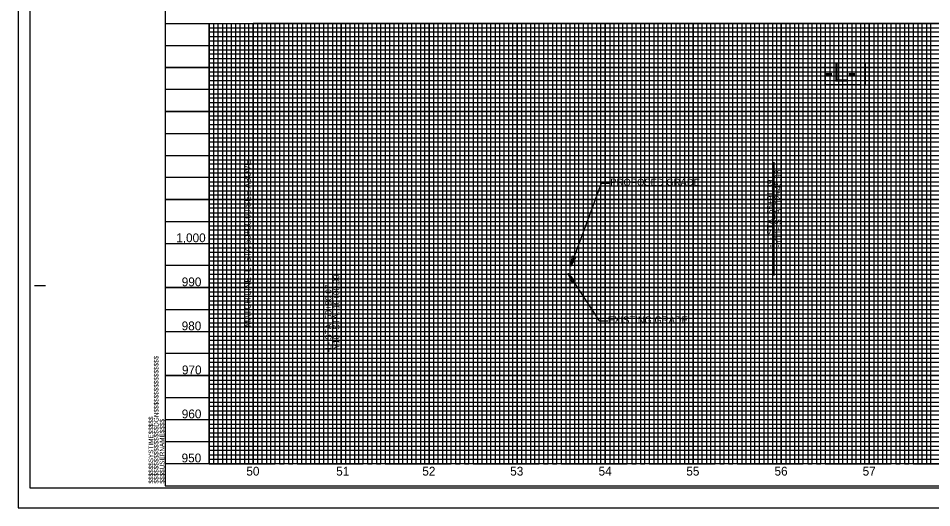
# Model space of a CAD drawing. Extents: x 1626113 to 1628102, y 900759 to 901859.
# Drawn here: x 1626113 to 1627151, y 900759 to 901315 of the extents above; entities that cross this region are included whole.
import ezdxf

# ---------------------------------------------------------------- set-up
doc = ezdxf.new("R2010")
doc.units = 0
for name, color, linetype in [('Default', 7, 'Continuous'), ('Matchline', 7, 'Continuous'), ('Matchline Text', 7, 'Continuous'), ('Prop DSN Text', 7, 'Continuous'), ('Prop PHM Black Shape', 7, 'Continuous'), ('Prop Plan Preparation Cover Label', 7, 'Continuous'), ('Scratch_Level_2', 7, 'Continuous'), ('Sheet Cutting Line CELL', 7, 'Continuous'), ('Sheet DOT Grid CELL', 7, 'Continuous'), ('Sheet Layout Profile Border Port 2', 7, 'Continuous'), ('Sheet Plot Border Inside CELL', 7, 'Continuous'), ('Sheet Plot Border Outside CELL', 7, 'Continuous'), ('Sheet Profile CELL', 7, 'Continuous'), ('Sheet Profile Grid Major CELL', 7, 'Continuous'), ('Sheet Profile Grid Middle CELL', 7, 'Continuous'), ('Typical Terminator CELL', 7, 'Continuous')]:
    doc.layers.add(name, color=color, linetype=linetype)

msp = doc.modelspace()

# ---------------------------------------------------------------- linework, layer by layer
at = {"layer": 'Matchline'}
msp.add_line((1626379.9, 900809.4), (1626379.9, 901309.4), dxfattribs=at)
at = {"layer": 'Prop DSN Text'}
for p, q in [((1626740.7, 901033.6), (1626775.7, 901127.8)), ((1626775.7, 901127.8), (1626785.7, 901127.8)), ((1626737.9, 901025.2), (1626772.9, 900971.5)), ((1626772.9, 900971.5), (1626782.9, 900971.5))]:
    msp.add_line(p, q, dxfattribs=at)
msp.add_lwpolyline([(1627029.9, 901264.4), (1627069.9, 901264.4), (1627069.9, 901239.4), (1627029.9, 901239.4)], close=True, dxfattribs=at)
for points in [[(1626971.7, 901022.9), (1626971.7, 901151.6)], [(1626469.9, 901046.4), (1626470, 900935.5)]]:
    msp.add_lwpolyline(points, dxfattribs=at)
at = {"layer": 'Prop PHM Black Shape'}
msp.add_lwpolyline([(1627024.9, 901264.4), (1627075, 901264.4), (1627075, 901239.2), (1627024.9, 901239.2)], close=True, dxfattribs=at)
at = {"layer": 'Prop Plan Preparation Cover Label'}
for p, q in [((1626329.9, 901304.2), (1627729.9, 901304.2)), ((1627729.9, 901299.2), (1626329.9, 901299.2)), ((1626329.9, 901294.2), (1627729.9, 901294.2)), ((1627729.9, 901289.2), (1626329.9, 901289.2)), ((1626329.9, 901279.2), (1627729.9, 901279.2)), ((1627729.9, 901274.2), (1626329.9, 901274.2)), ((1626329.9, 901269.2), (1627729.9, 901269.2)), ((1627729.9, 901264.2), (1626329.9, 901264.2)), ((1626329.9, 901254.2), (1627729.9, 901254.2)), ((1627729.9, 901249.2), (1626329.9, 901249.2)), ((1626329.9, 901244.2), (1627729.9, 901244.2)), ((1627729.9, 901239.2), (1626329.9, 901239.2)), ((1626329.9, 901229.2), (1627729.9, 901229.2)), ((1627729.9, 901224.2), (1626329.9, 901224.2)), ((1626329.9, 901219.2), (1627729.9, 901219.2)), ((1627729.9, 901214.2), (1626329.9, 901214.2)), ((1626329.9, 901204.2), (1627729.9, 901204.2)), ((1627729.9, 901199.2), (1626329.9, 901199.2)), ((1626329.9, 901194.2), (1627729.9, 901194.2)), ((1627729.9, 901189.2), (1626329.9, 901189.2)), ((1626329.9, 901179.2), (1627729.9, 901179.2)), ((1627729.9, 901174.2), (1626329.9, 901174.2)), ((1626329.9, 901169.2), (1627729.9, 901169.2)), ((1627729.9, 901164.2), (1626329.9, 901164.2)), ((1626329.9, 901154.2), (1627729.9, 901154.2)), ((1627729.9, 901149.2), (1626329.9, 901149.2)), ((1626329.9, 901144.2), (1627729.9, 901144.2)), ((1627729.9, 901139.2), (1626329.9, 901139.2)), ((1626329.9, 901129.2), (1627729.9, 901129.2)), ((1627729.9, 901124.2), (1626329.9, 901124.2)), ((1626329.9, 901119.2), (1627729.9, 901119.2)), ((1627729.9, 901114.2), (1626329.9, 901114.3)), ((1626329.9, 901104.2), (1627729.9, 901104.2)), ((1627729.9, 901099.2), (1626329.9, 901099.2)), ((1626329.9, 901094.2), (1627729.9, 901094.2)), ((1627729.9, 901089.2), (1626329.9, 901089.2)), ((1626329.9, 901079.2), (1627729.9, 901079.2)), ((1627729.9, 901074.2), (1626329.9, 901074.2)), ((1626329.9, 901069.2), (1627729.9, 901069.2)), ((1627729.9, 901064.2), (1626329.9, 901064.2)), ((1626329.9, 901054.2), (1627729.9, 901054.2)), ((1627729.9, 901049.2), (1626329.9, 901049.2)), ((1626329.9, 901044.2), (1627729.9, 901044.2)), ((1627729.9, 901039.2), (1626329.9, 901039.2)), ((1626329.9, 901029.2), (1627729.9, 901029.2)), ((1627729.9, 901024.2), (1626329.9, 901024.2)), ((1626329.9, 901019.2), (1627729.9, 901019.2)), ((1627729.9, 901014.2), (1626329.9, 901014.2)), ((1626329.9, 901004.2), (1627729.9, 901004.2)), ((1627729.9, 900999.2), (1626329.9, 900999.2)), ((1626329.9, 900994.2), (1627729.9, 900994.2)), ((1627729.9, 900989.2), (1626329.9, 900989.2)), ((1626329.9, 900979.2), (1627729.9, 900979.2)), ((1627729.9, 900974.2), (1626329.9, 900974.2)), ((1626329.9, 900969.2), (1627729.9, 900969.2)), ((1627729.9, 900964.2), (1626329.9, 900964.2)), ((1626329.9, 900954.2), (1627729.9, 900954.2)), ((1627729.9, 900949.2), (1626329.9, 900949.2)), ((1626329.9, 900944.2), (1627729.9, 900944.2)), ((1627729.9, 900939.2), (1626329.9, 900939.2)), ((1626329.9, 900929.2), (1627729.9, 900929.2)), ((1627729.9, 900924.2), (1626329.9, 900924.2)), ((1626329.9, 900919.2), (1627729.9, 900919.2)), ((1627729.9, 900914.2), (1626329.9, 900914.2)), ((1626329.9, 900904.2), (1627729.9, 900904.2)), ((1627729.9, 900899.2), (1626329.9, 900899.2)), ((1626329.9, 900894.2), (1627729.9, 900894.2)), ((1627729.9, 900889.2), (1626329.9, 900889.2)), ((1626329.9, 900879.2), (1627729.9, 900879.2)), ((1627729.9, 900874.2), (1626329.9, 900874.2)), ((1626329.9, 900869.2), (1627729.9, 900869.2)), ((1627729.9, 900864.2), (1626329.9, 900864.2)), ((1626329.9, 900854.2), (1627729.9, 900854.2)), ((1627729.9, 900849.2), (1626329.9, 900849.2)), ((1626329.9, 900844.2), (1627729.9, 900844.2)), ((1627729.9, 900839.2), (1626329.9, 900839.2)), ((1626329.9, 900829.2), (1627729.9, 900829.2)), ((1627729.9, 900824.2), (1626329.9, 900824.2)), ((1626329.9, 900819.2), (1627729.9, 900819.2)), ((1626329.9, 900814.2), (1627729.9, 900814.2))]:
    msp.add_line(p, q, dxfattribs=at)
for points in [[(1626329.9, 901309.2), (1626334.9, 901309.2), (1626334.9, 900809.2), (1626339.9, 900809.2), (1626339.9, 901309.2), (1626344.9, 901309.2), (1626344.9, 900809.2), (1626349.9, 900809.2), (1626349.9, 901309.2), (1626359.9, 901309.2), (1626359.9, 900809.2), (1626364.9, 900809.2), (1626364.9, 901309.2), (1626369.9, 901309.2), (1626369.9, 900809.2), (1626374.9, 900809.2), (1626384.9, 900809.2), (1626389.9, 900809.2), (1626389.9, 901309.2), (1626394.9, 901309.2), (1626394.9, 900809.2), (1626399.9, 900809.2), (1626399.9, 901309.2), (1626409.9, 901309.2), (1626409.9, 900809.2), (1626414.9, 900809.2), (1626414.9, 901309.2), (1626419.9, 901309.2), (1626419.9, 900809.2), (1626424.9, 900809.2), (1626424.9, 901309.2), (1626434.9, 901309.2), (1626434.9, 900809.2), (1626439.9, 900809.2), (1626439.9, 901309.2), (1626444.9, 901309.2), (1626444.9, 900809.2), (1626449.9, 900809.2), (1626449.9, 901309.2), (1626459.9, 901309.2), (1626459.9, 900809.2), (1626464.9, 900809.2), (1626464.9, 901309.2), (1626469.9, 901309.2), (1626469.9, 900809.2), (1626474.9, 900809.2), (1626474.9, 901309.2), (1626484.9, 901309.2), (1626484.9, 900809.2), (1626489.9, 900809.2), (1626489.9, 901309.2), (1626494.9, 901309.2), (1626494.9, 900809.2), (1626499.9, 900809.2), (1626499.9, 901309.2), (1626509.9, 901309.2), (1626509.9, 900809.2), (1626514.9, 900809.2), (1626514.9, 901309.2), (1626519.9, 901309.2), (1626519.9, 900809.2), (1626524.9, 900809.2), (1626524.9, 901309.2), (1626534.9, 901309.2), (1626534.9, 900809.2), (1626539.9, 900809.2), (1626539.9, 901309.2), (1626544.9, 901309.2), (1626544.9, 900809.2)], [(1626374.9, 900809.2), (1626374.9, 901309.2), (1626384.9, 901309.2), (1626384.9, 900809.2)], [(1626544.9, 900809.2), (1626549.9, 900809.2), (1626549.9, 901309.2), (1626559.9, 901309.2), (1626559.9, 900809.2), (1626564.9, 900809.2), (1626564.9, 901309.2), (1626569.9, 901309.2), (1626569.9, 900809.2), (1626574.9, 900809.2), (1626574.9, 901309.2), (1626584.9, 901309.2), (1626584.9, 900809.2), (1626589.9, 900809.2), (1626589.9, 901309.2), (1626594.9, 901309.2), (1626594.9, 900809.2), (1626599.9, 900809.2), (1626599.9, 901309.2), (1626609.9, 901309.2), (1626609.9, 900809.2), (1626614.9, 900809.2), (1626614.9, 901309.2), (1626619.9, 901309.2), (1626619.9, 900809.2), (1626624.9, 900809.2), (1626624.9, 901309.2), (1626634.9, 901309.2), (1626634.9, 900809.2), (1626639.9, 900809.2), (1626639.9, 901309.2), (1626644.9, 901309.2), (1626644.9, 900809.2), (1626649.9, 900809.2), (1626649.9, 901309.2), (1626659.9, 901309.2), (1626659.9, 900809.2), (1626664.9, 900809.2), (1626664.9, 901309.2), (1626669.9, 901309.2), (1626669.9, 900809.2), (1626674.9, 900809.2), (1626674.9, 901309.2), (1626684.9, 901309.2), (1626684.9, 900809.2), (1626689.9, 900809.2), (1626689.9, 901309.2), (1626694.9, 901309.2), (1626694.9, 900809.2), (1626699.9, 900809.2), (1626699.9, 901309.2), (1626709.9, 901309.2), (1626709.9, 900809.2), (1626714.9, 900809.2), (1626714.9, 901309.2), (1626719.9, 901309.2), (1626719.9, 900809.2), (1626724.9, 900809.2), (1626724.9, 901309.2), (1626734.9, 901309.2), (1626734.9, 900809.2), (1626739.9, 900809.2), (1626739.9, 901309.2), (1626744.9, 901309.2), (1626744.9, 900809.2), (1626749.9, 900809.2), (1626749.9, 901309.2), (1626759.9, 901309.2), (1626759.9, 900809.2), (1626764.9, 900809.2), (1626764.9, 901309.2), (1626769.9, 901309.2), (1626769.9, 900809.2), (1626774.9, 900809.2), (1626774.9, 901309.2), (1626784.9, 901309.2), (1626784.9, 900809.2), (1626789.9, 900809.2), (1626789.9, 901309.2), (1626794.9, 901309.2), (1626794.9, 900809.2), (1626799.9, 900809.2), (1626799.9, 901309.2), (1626809.9, 901309.2), (1626809.9, 900809.2), (1626814.9, 900809.2), (1626814.9, 901309.2), (1626819.9, 901309.2), (1626819.9, 900809.2), (1626824.9, 900809.2), (1626824.9, 901309.2), (1626834.9, 901309.2), (1626834.9, 900809.2), (1626839.9, 900809.2), (1626839.9, 901309.2), (1626844.9, 901309.2), (1626844.9, 900809.2), (1626849.9, 900809.2), (1626849.9, 901309.2), (1626859.9, 901309.2)], [(1626859.9, 901309.2), (1626859.9, 900809.2), (1626864.9, 900809.2), (1626864.9, 901309.2), (1626869.9, 901309.2), (1626869.9, 900809.2), (1626874.9, 900809.2), (1626874.9, 901309.2), (1626884.9, 901309.2), (1626884.9, 900809.2), (1626889.9, 900809.2), (1626889.9, 901309.2), (1626894.9, 901309.2), (1626894.9, 900809.2), (1626899.9, 900809.2), (1626899.9, 901309.2), (1626909.9, 901309.2), (1626909.9, 900809.2), (1626914.9, 900809.2), (1626914.9, 901309.2), (1626919.9, 901309.2), (1626919.9, 900809.2), (1626924.9, 900809.2), (1626924.9, 901309.2), (1626934.9, 901309.2), (1626934.9, 900809.2), (1626939.9, 900809.2), (1626939.9, 901309.2), (1626944.9, 901309.2), (1626944.9, 900809.2), (1626949.9, 900809.2), (1626949.9, 901309.2), (1626959.9, 901309.2), (1626959.9, 900809.2), (1626964.9, 900809.2), (1626964.9, 901309.2), (1626969.9, 901309.2), (1626969.9, 900809.2), (1626974.9, 900809.2), (1626974.9, 901309.2), (1626984.9, 901309.2), (1626984.9, 900809.2), (1626984.9, 900809.2), (1626989.9, 900809.2), (1626989.9, 901309.2), (1626994.9, 901309.2), (1626994.9, 900809.2), (1626999.9, 900809.2), (1626999.9, 901309.2), (1627009.9, 901309.2), (1627009.9, 900809.2), (1627014.9, 900809.2), (1627014.9, 901309.2), (1627019.9, 901309.2), (1627019.9, 900809.2), (1627024.9, 900809.2), (1627024.9, 901309.2), (1627034.9, 901309.2), (1627034.9, 900809.2), (1627039.9, 900809.2), (1627039.9, 901309.2), (1627044.9, 901309.2), (1627044.9, 900809.2), (1627049.9, 900809.2), (1627049.9, 901309.2), (1627059.9, 901309.2), (1627059.9, 900809.2), (1627064.9, 900809.2), (1627064.9, 901309.2), (1627069.9, 901309.2), (1627069.9, 900809.2), (1627074.9, 900809.2), (1627074.9, 901309.2), (1627084.9, 901309.2), (1627084.9, 900809.2), (1627089.9, 900809.2), (1627089.9, 901309.2), (1627094.9, 901309.2), (1627094.9, 900809.2), (1627099.9, 900809.2), (1627099.9, 901309.2), (1627109.9, 901309.2), (1627109.9, 900809.2), (1627114.9, 900809.2), (1627114.9, 901309.2), (1627119.9, 901309.2), (1627119.9, 900809.2), (1627124.9, 900809.2), (1627124.9, 901309.2), (1627134.9, 901309.2), (1627134.9, 900809.2), (1627139.6, 900809.7), (1627139.9, 900809.2), (1627139.9, 901309.2), (1627144.9, 901309.2), (1627144.9, 900809.2), (1627149.9, 900809.2), (1627149.9, 901309.2), (1627159.9, 901309.2)]]:
    msp.add_lwpolyline(points, dxfattribs=at)
at = {"layer": 'Scratch_Level_2'}
msp.add_lwpolyline([(1626379.9, 900809.4), (1627729.9, 900809.4), (1627729.9, 901309.2), (1626379.9, 901309.2)], close=True, dxfattribs=at)
at = {"layer": 'Sheet Cutting Line CELL'}
for p, q in [((1626112.9, 901859.2), (1626112.9, 900759.2)), ((1626112.9, 900759.2), (1627796.9, 900759.2))]:
    msp.add_line(p, q, dxfattribs=at)
at = {"layer": 'Sheet DOT Grid CELL'}
for p, q in [((1626279.9, 901309.2), (1627779.8, 901309.2)), ((1626329.9, 901309.2), (1626329.9, 900809.2)), ((1626379.9, 901309.2), (1626379.9, 900809.2)), ((1626429.9, 901309.2), (1626429.9, 900809.2)), ((1626479.9, 901309.2), (1626479.9, 900809.2)), ((1626529.9, 901309.2), (1626529.9, 900809.2)), ((1626579.9, 901309.2), (1626579.9, 900809.2)), ((1626629.9, 901309.2), (1626629.9, 900809.2)), ((1626679.9, 901309.2), (1626679.9, 900809.2)), ((1626729.9, 901309.2), (1626729.9, 900809.2)), ((1626779.9, 901309.2), (1626779.9, 900809.2)), ((1626829.9, 901309.2), (1626829.9, 900809.2)), ((1626879.9, 901309.2), (1626879.9, 900809.2)), ((1626929.9, 901309.2), (1626929.9, 900809.2)), ((1626979.9, 901309.2), (1626979.9, 900809.2)), ((1627029.9, 901309.2), (1627029.9, 900809.2)), ((1627079.9, 901309.2), (1627079.9, 900809.2)), ((1627129.9, 901309.2), (1627129.9, 900809.2)), ((1626279.9, 901259.2), (1627779.8, 901259.2)), ((1626279.9, 901209.2), (1627779.8, 901209.2)), ((1626279.9, 901159.2), (1627779.8, 901159.2)), ((1626279.9, 901109.2), (1627779.8, 901109.2)), ((1626279.9, 901059.2), (1627779.8, 901059.2)), ((1626279.9, 901009.2), (1627779.8, 901009.2)), ((1626279.9, 900959.2), (1627779.8, 900959.2)), ((1626279.9, 900909.2), (1627779.8, 900909.2)), ((1626279.9, 900859.2), (1627779.8, 900859.2))]:
    msp.add_line(p, q, dxfattribs=at)
at = {"layer": 'Sheet Layout Profile Border Port 2'}
msp.add_lwpolyline([(1626329.9, 901309.2), (1627729.9, 901309.2), (1627729.9, 900809.2), (1626329.9, 900809.2)], close=True, dxfattribs=at)
at = {"layer": 'Sheet Plot Border Inside CELL'}
msp.add_lwpolyline([(1626125.9, 900781.6), (1627792.4, 900781.6), (1627792.4, 901836.7), (1626125.9, 901836.7)], close=True, dxfattribs=at)
at = {"layer": 'Sheet Plot Border Outside CELL'}
msp.add_lwpolyline([(1626112.9, 900759.2), (1627796.9, 900759.2), (1627796.9, 901859.2), (1626112.9, 901859.2)], close=True, dxfattribs=at)
at = {"layer": 'Sheet Profile CELL'}
for p, q in [((1626279.9, 901309.2), (1627779.9, 901309.2)), ((1626131.4, 901011.7), (1626143.9, 901011.7)), ((1627779.9, 900809.2), (1626279.9, 900809.2)), ((1626279.9, 900784.2), (1627779.9, 900784.2)), ((1626279.9, 900784.2), (1626279.9, 900784.2)), ((1626279.9, 900784.2), (1626279.9, 900784.2)), ((1626279.9, 900784.2), (1626279.9, 900784.2)), ((1626279.9, 900784.2), (1626279.9, 900784.2)), ((1626279.9, 900784.2), (1626279.9, 900784.2)), ((1626279.9, 900784.2), (1626279.9, 900784.2)), ((1626279.9, 900784.2), (1626279.9, 900784.2))]:
    msp.add_line(p, q, dxfattribs=at)
msp.add_lwpolyline([(1627779.9, 901834.2), (1626279.9, 901834.2), (1626279.9, 900784.2), (1627779.9, 900784.2)], close=True, dxfattribs=at)
msp.add_lwpolyline([(1626317.4, 900784.2), (1626317.4, 900784.2)], dxfattribs=at)
at = {"layer": 'Sheet Profile Grid Major CELL'}
for p, q in [((1626779.9, 901309.2), (1626829.9, 901309.2)), ((1626879.9, 901309.2), (1626929.9, 901309.2)), ((1626979.9, 901309.2), (1627029.9, 901309.2)), ((1627079.9, 901309.2), (1627129.9, 901309.2)), ((1626279.9, 900809.2), (1626279.9, 900809.2))]:
    msp.add_line(p, q, dxfattribs=at)
for points in [[(1626329.9, 901309.2), (1626329.9, 900809.2), (1626379.9, 900809.2), (1626379.9, 901309.2), (1626429.9, 901309.2), (1626429.9, 900809.2), (1626479.9, 900809.2), (1626479.9, 901309.2), (1626529.9, 901309.2), (1626529.9, 900809.2), (1626579.9, 900809.2), (1626579.9, 901309.2), (1626629.9, 901309.2), (1626629.9, 900809.2), (1626679.9, 900809.2), (1626679.9, 901309.2), (1626729.9, 901309.2), (1626729.9, 900809.2), (1626779.9, 900809.2), (1626779.9, 901309.2), (1626829.9, 901309.2), (1626829.9, 900809.2), (1626879.9, 900809.2), (1626879.9, 901309.2), (1626929.9, 901309.2), (1626929.9, 900809.2), (1626979.9, 900809.2), (1626979.9, 901309.2), (1627029.9, 901309.2), (1627029.9, 900809.2), (1627079.9, 900809.2), (1627079.9, 901309.2), (1627129.9, 901309.2), (1627129.9, 900809.2), (1627179.9, 900809.2)], [(1627779.9, 901259.2), (1626279.9, 901259.2)], [(1627779.9, 901209.2), (1626279.9, 901209.2), (1626279.9, 901159.2), (1627779.9, 901159.2)], [(1627779.9, 901109.2), (1626279.9, 901109.2), (1626279.9, 901059.2), (1627779.9, 901059.2)], [(1627779.9, 901009.2), (1626279.9, 901009.2), (1626279.9, 900959.2), (1627779.9, 900959.2)], [(1627779.9, 900909.2), (1626279.9, 900909.2), (1626279.9, 900909.2), (1626279.9, 900859.2), (1627779.9, 900859.2)], [(1627779.9, 900809.2), (1626279.9, 900809.2)]]:
    msp.add_lwpolyline(points, dxfattribs=at)
at = {"layer": 'Sheet Profile Grid Middle CELL'}
for points in [[(1626304.9, 901309.2), (1626354.9, 901309.2), (1626354.9, 900809.2), (1626404.9, 900809.2), (1626404.9, 901309.2), (1626454.9, 901309.2), (1626454.9, 900809.2), (1626504.9, 900809.2), (1626504.9, 901309.2), (1626554.9, 901309.2), (1626554.9, 900809.2), (1626604.9, 900809.2), (1626604.9, 901309.2), (1626654.9, 901309.2), (1626654.9, 900809.2), (1626704.9, 900809.2), (1626704.9, 901309.2), (1626754.9, 901309.2), (1626754.9, 900809.2), (1626804.9, 900809.2), (1626804.9, 901309.2), (1626854.9, 901309.2), (1626854.9, 900809.2), (1626904.9, 900809.2), (1626904.9, 900809.2), (1626904.9, 901309.2), (1626954.9, 901309.2), (1626954.9, 900809.2), (1627004.9, 900809.2), (1627004.9, 901309.2), (1627054.9, 901309.2), (1627054.9, 900809.2), (1627104.9, 900809.2), (1627104.9, 901309.2), (1627154.9, 901309.2)], [(1626279.9, 901284.2), (1627779.9, 901284.2)], [(1627779.9, 901234.2), (1626279.9, 901234.2), (1626279.9, 901184.2), (1627779.9, 901184.2)], [(1627779.9, 901134.2), (1626279.9, 901134.2), (1626279.9, 901084.2), (1627779.9, 901084.2)], [(1627779.9, 901034.2), (1626279.9, 901034.2), (1626279.9, 900984.2), (1627779.9, 900984.2)], [(1627779.9, 900934.2), (1626279.9, 900934.2), (1626279.9, 900884.2), (1627779.9, 900884.2)], [(1627779.9, 900834.2), (1626279.9, 900834.2)]]:
    msp.add_lwpolyline(points, dxfattribs=at)
at = {"layer": 'Typical Terminator CELL'}
for points in [[(1626746.6, 901043.9), (1626740.7, 901033.6), (1626742.8, 901045.4), (1626744.2, 901043.3)], [(1626742.6, 901014.3), (1626737.9, 901025.2), (1626746, 901016.5), (1626743.5, 901016.6)]]:
    msp.add_lwpolyline(points, close=True, dxfattribs=at)

# ---------------------------------------------------------------- texts
at = {"layer": 'Default'}
for s, p in [('1,000', (1626292.4, 901060.7)), ('990', (1626298.7, 901010.7)), ('980', (1626298.6, 900960.7)), ('970', (1626298.9, 900910.7)), ('960', (1626298.7, 900860.7)), ('950', (1626298.5, 900810.7)), ('50', (1626372.1, 900795.7)), ('51', (1626474.2, 900795.7)), ('52', (1626572, 900795.7)), ('53', (1626671.9, 900795.7)), ('54', (1626772.3, 900795.7)), ('55', (1626872, 900795.7)), ('56', (1626972.2, 900795.7)), ('57', (1627072.3, 900795.7))]:
    msp.add_text(s, height=10, dxfattribs=at).set_placement(p)
at = {"layer": 'Matchline Text'}
msp.add_text('MATCH LINE -L- STA 50+00.00 SEE ABOVE', height=7, rotation=90, dxfattribs=at).set_placement((1626376.9, 900964.4))
at = {"layer": 'Prop DSN Text'}
for s, height, p in [('-L-', 21.88, (1627029.2, 901243.1)), ('PROPOSED GRADE', 8, (1626785.7, 901124.8)), ('EXISTING GRADE', 8, (1626782.9, 900968.5))]:
    msp.add_text(s, height=height, dxfattribs=at).set_placement(p)
for s, p in [('-Y11- STA. 12+45.98', (1626979.5, 901055)), ('-L- STA. 55+91.39', (1626970.7, 901055)), ('-Y10- STA. 10+00.00', (1626477.7, 900935.8)), ('-L- STA. 50+90.07', (1626468.8, 900935.8))]:
    msp.add_text(s, height=7, rotation=90, dxfattribs=at).set_placement(p)
at = {"layer": 'Sheet Profile CELL'}
for s, p in [('$$$$$$$$$$$$$$$$DGN$$$$$$$$$$$$$$$$', (1626272.3, 900786.6)), ('$$$$$$SYSTIME$$$$$', (1626266.3, 900786.6)), ('$$$$USERNAME$$$$', (1626278.9, 900786.6))]:
    msp.add_text(s, height=5.25, rotation=90, dxfattribs=at).set_placement(p)

doc.saveas('drawing.dxf')
